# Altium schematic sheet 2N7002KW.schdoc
size 127 x 101 mm
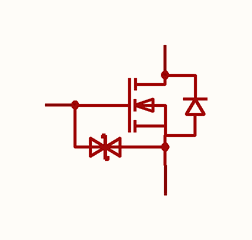
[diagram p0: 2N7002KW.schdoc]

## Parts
Q?  2n7002kw_c504047  [SOT-323-3_L2.0-W1.3-P1.30-LS2.1-BR]  (value not drawn)

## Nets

Not connected (* = marked no-connect by the designer): Q? 1(G) 2(S) 3(D)

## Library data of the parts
Q? = 2n7002kw_c504047: 数量:1个N沟道;漏源电压(Vdss):60V;连续漏极电流(Id):340mA;导通电阻(RDS(on)):2.5Ω@10V;耗散功率(Pd):200mW;阈值电压(Vgs(th)):2.5V;; Manufacturer: CJ(江苏长电/长晶); AddInBom: yes; ModelId: 59529c0d6fc749f28f2d0659e12986b4; ModelName: SOT-323-3_L2.0-W1.3-H1.0-LS2.1-P1.30; ModelTransform: 78.74,82.677,0,90,0,0,0.0005,0,0; Number: 1个N沟道; Drain to Source Voltage: 60V; Current - Continuous Drain(Id): 340mA; Pd - Power Dissipation: 200mW; Gate Threshold Voltage (Vgs(th)): 2.5V; Input Capacitance(Ciss): 40pF; Reverse Transfer Capacitance (Crss@Vds): 10pF; Type: N沟道; Output Capacitance(Coss): 30pF; Vgs: ±20V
